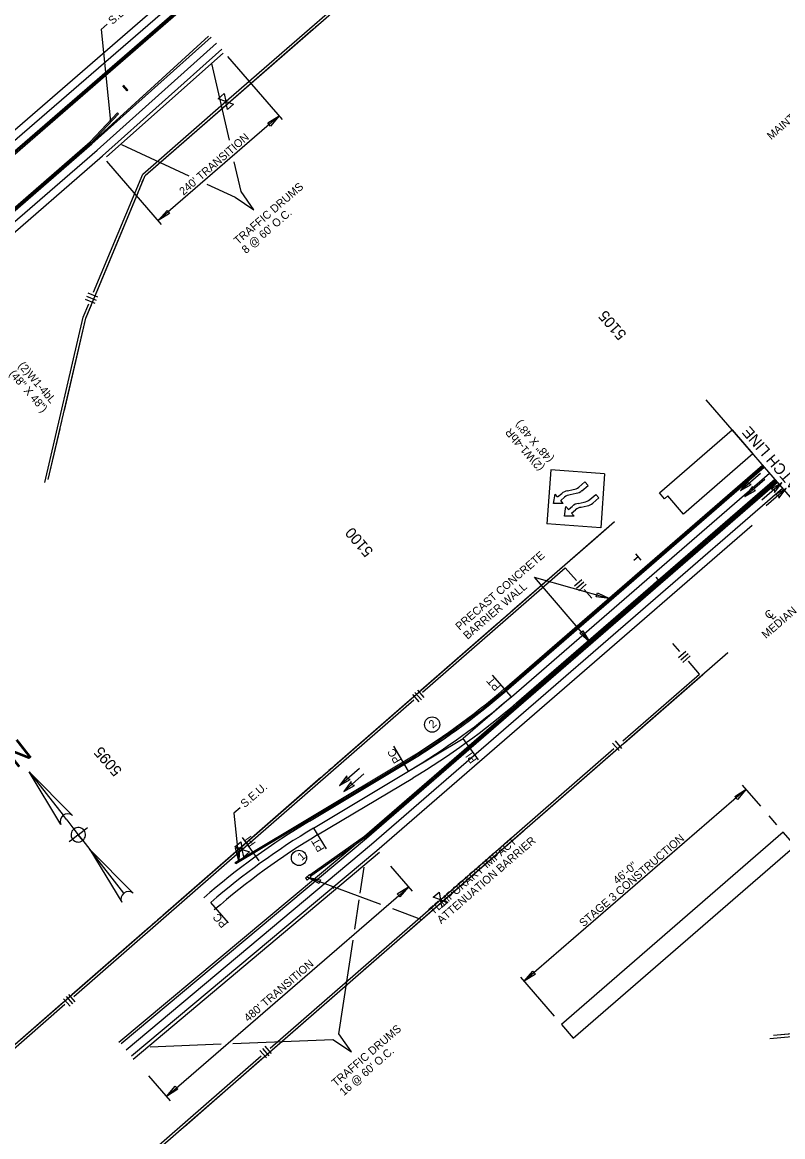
# Model space of a CAD drawing. Extents: x 259983 to 267998, y 211467 to 219827.
# Drawn here: x 263924 to 265064, y 214746 to 216417 of the extents above; entities that cross this region are included whole.
import ezdxf

# ---------------------------------------------------------------- set-up
doc = ezdxf.new("R2010")
doc.units = 0
for name, color, linetype in [('1', 7, 'Continuous'), ('DRAINAGE', 7, 'Continuous'), ('Level 1', 7, 'Continuous'), ('Level 43', 7, 'Continuous'), ('Level 58', 7, 'Continuous'), ('R-W - CofA', 7, 'Continuous'), ('R_MOT', 7, 'Continuous'), ('R_MOT STAGE 1', 7, 'Continuous'), ('R_MOT STAGE 2', 7, 'Continuous'), ('STATIONING1', 7, 'Continuous')]:
    doc.layers.add(name, color=color, linetype=linetype)

msp = doc.modelspace()

# ---------------------------------------------------------------- linework, layer by layer
at = {"layer": '1'}
for p, q in [((264051, 216413.6), (264042.1, 216405.9)), ((264042.1, 216405.9), (264056.1, 216267.8)), ((264691.6, 215585.1), (264804.6, 215552.9)), ((264691.6, 215585.1), (264775.2, 215487.6)), ((265031.6, 215241.6), (265004.3, 215273)), ((265009.6, 215267), (264676.8, 214979)), ((264250.5, 215239.1), (264241.2, 215231.1)), ((264241.2, 215231.1), (264248.6, 215159.4)), ((265055.7, 215213.6), (265044, 215227.2)), ((264461.7, 215094.3), (264351.4, 215135.2)), ((264523.3, 215071.4), (264479.6, 215087.6)), ((264532.1, 215079.1), (264523.3, 215071.4)), ((264722, 214926.8), (264671.4, 214985.4))]:
    msp.add_line(p, q, dxfattribs=at)
for points in [[(264234.5, 216240.1), (264208.1, 216354.8)], [(264072.9, 216233.3), (264173.6, 216186.5)], [(264200.6, 216174), (264243.1, 216154.3), (264271.2, 216135.7), (264252.2, 216162.9), (264241.9, 216207.6)], [(264430.6, 215111.2), (264436.5, 215149.9)], [(264422.5, 215057.3), (264429.2, 215101.4)], [(264239.5, 214885.8), (264389.8, 214891.9), (264417.9, 214873.4), (264398.9, 214900.5), (264420, 215040.7)], [(264115.9, 214880.8), (264222.2, 214885.1)]]:
    msp.add_lwpolyline(points, dxfattribs=at)
for points in [[(264292.4, 216265.7), (264309.4, 216276.4), (264296.4, 216261.1)], [(264144.9, 216129.9), (264127.9, 216119.3), (264141, 216134.5)], [(264786.4, 215561.2), (264804.6, 215552.9), (264784.8, 215555.4)], [(264764.6, 215504.6), (264775.2, 215487.6), (264760.1, 215500.7)], [(264992.6, 215256.3), (265009.6, 215267), (264996.6, 215251.7)], [(264249.6, 215179.4), (264248.6, 215159.4), (264243.6, 215178.8)], [(264369, 215125.5), (264351.4, 215135.2), (264371, 215131.1)], [(264486, 215110), (264502.9, 215120.7), (264489.9, 215105.5)], [(264693.8, 214989.7), (264676.8, 214979), (264689.8, 214994.3)], [(264157, 214817.2), (264140, 214806.5), (264153, 214821.7)]]:
    msp.add_lwpolyline(points, close=True, dxfattribs=at)
at = {"layer": 'DRAINAGE'}
for p, q in [((264081.2, 216313.8), (264074.7, 216321.3)), ((264082.4, 216314.8), (264075.8, 216322.3)), ((264081.2, 216313.8), (264082.4, 216314.8))]:
    msp.add_line(p, q, dxfattribs=at)
at = {"layer": 'Level 1'}
for p, q in [((263934.2, 215293.1), (263999, 215227.7)), ((263981.9, 215214.3), (263934.2, 215293.1)), ((263934.2, 215293.1), (263985.1, 215227.9)), ((263990.5, 215221), (263985.1, 215227.9)), ((263990.5, 215221), (264001.2, 215207.3)), ((264001.2, 215207.3), (264007.9, 215198.7)), ((264007.9, 215198.7), (264016.5, 215205.4)), ((264016.5, 215205.4), (264021.6, 215209.5)), ((264016.5, 215205.4), (264016.5, 215205.4)), ((263999, 215191.8), (263994.2, 215188)), ((264007.9, 215198.7), (263999.6, 215192.2)), ((264007.9, 215198.7), (264014.6, 215190.2)), ((264014.6, 215190.2), (264007.9, 215198.7)), ((264014.6, 215190.2), (264025.3, 215176.4)), ((264025.3, 215176.4), (264073, 215097.7)), ((264076.2, 215111.2), (264025.3, 215176.4)), ((264025.3, 215176.4), (264090.2, 215111.1))]:
    msp.add_line(p, q, dxfattribs=at)
for centre, radius, start, end in [((263992, 215219.1), 11.2, 128, 205.3196), ((263992, 215219.1), 11.2, 50.6804, 128), ((264007.9, 215198.7), 10.9, 128, 218), ((264007.9, 215198.7), 10.9, 38, 128), ((264007.9, 215198.7), 10.9, 308, 38), ((264007.9, 215198.7), 10.9, 218, 308), ((264083.1, 215102.4), 11.2, 128, 205.3196), ((264083.1, 215102.4), 11.2, 50.6804, 128)]:
    msp.add_arc(centre, radius, start, end, dxfattribs=at)
at = {"layer": 'Level 43'}
for points in [[(265001.2, 215714.8), (265031.3, 215740.7)], [(265007.8, 215706), (265037.8, 215732)], [(265063, 215726.4), (265033, 215700.4)], [(265069.6, 215717.7), (265039.6, 215691.7)], [(264399.6, 215272.5), (264429.7, 215298.5)], [(264406.2, 215263.8), (264436.2, 215289.8)]]:
    msp.add_lwpolyline(points, dxfattribs=at)
at = {"layer": 'Level 58'}
for points in [[(265012.4, 215729.4), (265001.2, 215714.8), (265017.3, 215723.7), (265012.6, 215724.6)], [(265051.9, 215711.8), (265063, 215726.4), (265047, 215717.5), (265051.7, 215716.6)], [(265018.9, 215720.7), (265007.8, 215706), (265023.8, 215715), (265019.1, 215715.9)], [(265058.4, 215703.1), (265069.6, 215717.7), (265053.5, 215708.7), (265058.2, 215707.9)], [(264410.8, 215287.2), (264399.6, 215272.5), (264415.7, 215281.5), (264411, 215282.4)], [(264417.4, 215278.4), (264406.2, 215263.8), (264422.2, 215272.8), (264417.5, 215273.6)]]:
    msp.add_lwpolyline(points, close=True, dxfattribs=at)
at = {"layer": 'R-W - CofA'}
for p, q in [((264217.7, 216301.9), (264226.9, 216309.9)), ((264226.9, 216309.9), (264229.3, 216297.9)), ((264229.3, 216297.9), (264217.7, 216301.9)), ((264231.6, 216285.9), (264229.3, 216297.9)), ((264229.3, 216297.9), (264240.8, 216294)), ((264240.8, 216294), (264231.6, 216285.9)), ((264020.2, 216006.3), (264034.5, 216000.3)), ((264022.2, 216011), (264036.5, 216005.1)), ((264018.2, 216001.5), (264032.6, 215995.5)), ((263962.8, 215731.4), (264019.3, 215973.1)), ((264738.3, 215599), (264755.1, 215579.7)), ((264752.1, 215572), (264763.1, 215581.6)), ((264755.3, 215568.3), (264766.3, 215578)), ((264758.5, 215564.6), (264769.5, 215574.3)), ((264766.6, 215566.5), (264778.1, 215553.3)), ((264910, 215473.4), (264899.7, 215485.3)), ((264908.2, 215464.4), (264919.2, 215474)), ((264911.4, 215460.7), (264922.4, 215470.3)), ((264914.6, 215457), (264925.6, 215466.7)), ((264939.4, 215439.7), (264922.9, 215458.7)), ((264509.2, 215409), (264518.8, 215398)), ((264512.8, 215412.2), (264522.5, 215401.2)), ((264516.5, 215415.4), (264526.1, 215404.4)), ((264812.9, 215339.4), (264822.7, 215328.2)), ((264809.2, 215336.1), (264818.9, 215324.9)), ((264242.9, 215180.5), (264251.6, 215188.1)), ((264251.6, 215188.1), (264253.8, 215176.8)), ((264253.8, 215176.8), (264242.9, 215180.5)), ((264256, 215165.5), (264253.8, 215176.8)), ((264253.8, 215176.8), (264264.7, 215173.1)), ((264264.7, 215173.1), (264256, 215165.5)), ((264540.1, 215105.2), (264548.9, 215112.8)), ((264551.1, 215101.4), (264540.1, 215105.2)), ((264548.9, 215112.8), (264551.1, 215101.4)), ((264553.4, 215090), (264551.1, 215101.4)), ((264551.1, 215101.4), (264562.1, 215097.7)), ((264562.1, 215097.7), (264553.4, 215090)), ((263989.5, 214956.2), (263999.2, 214945.2)), ((263993.2, 214959.4), (264002.8, 214948.4)), ((263985.8, 214953), (263995.5, 214942)), ((265050.7, 214898.1), (265362.9, 214926.4)), ((264280.3, 214875.2), (264290, 214864.1)), ((264284, 214878.5), (264293.7, 214867.3)), ((264287.7, 214881.7), (264297.4, 214870.6))]:
    msp.add_line(p, q, dxfattribs=at)
for points in [[(264019.3, 215973.1), (264108, 216186.8), (264635.8, 216646.6), (264947.8, 216943)], [(264233.9, 216301.9), (264501.9, 216535.5)], [(264363.9, 216409.7), (264368.6, 216413.8)], [(264236.6, 216298.8), (264359.9, 216406.2)], [(264030.9, 216011.9), (264104.5, 216189.2), (264233.9, 216301.9)], [(264108.7, 216187.3), (264236.6, 216298.8)], [(264103.9, 216176.9), (264106.3, 216182.7)], [(264034.8, 216010.3), (264097.5, 216161.4)], [(264099.5, 216166.2), (264101.9, 216172)], [(263957.5, 215726.7), (264015.4, 215974.4), (264023.8, 215994.7)], [(263987, 215834.9), (264019.3, 215973.1), (264027.6, 215993.1)], [(263984.4, 215823.6), (263985.8, 215829.8)], [(263962.8, 215731.4), (263980.5, 215807.3)], [(263981.7, 215812.4), (263983.2, 215818.5)], [(263865, 214843.2), (264812.1, 215668.4)], [(264778.9, 215639.5), (264812.1, 215668.4)], [(264658.2, 215534.4), (264778.9, 215639.5)], [(264524.3, 215412.5), (264738.3, 215599)], [(264641.8, 215520), (264646.3, 215523.9)], [(264650, 215527.2), (264654.5, 215531.1)], [(264521.7, 215415.4), (264638, 215516.8)], [(264029.2, 214641.4), (264982.3, 215471.9)], [(264965.1, 215456.9), (264982.3, 215471.9)], [(264824.5, 215339.6), (264939.4, 215439.7)], [(264827.1, 215336.6), (264944.7, 215439.1)], [(264948.4, 215442.4), (264953, 215446.3)], [(264956.8, 215449.6), (264961.3, 215453.6)], [(264258.2, 215180.6), (264511, 215400.9)], [(264392.1, 215302.5), (264508.5, 215403.9)], [(264555.5, 215105.2), (264811.1, 215327.9)], [(264696.1, 215222.5), (264813.7, 215325)], [(264375.7, 215288.2), (264380.2, 215292.1)], [(264383.9, 215295.3), (264388.4, 215299.2)], [(264255.6, 215183.5), (264371.9, 215284.9)], [(264558.1, 215102.3), (264675.7, 215204.7)], [(264679.5, 215208), (264684, 215212)], [(264687.8, 215215.3), (264692.3, 215219.2)], [(264001, 214956.5), (264258.2, 215180.6)], [(264134.9, 215078.4), (264255.6, 215183.5)], [(264295.5, 214878.7), (264555.5, 215105.2)], [(264436.1, 214996), (264558.1, 215102.3)], [(264126.7, 215071.2), (264131.2, 215075.1)], [(263998.4, 214959.4), (264114.7, 215060.8)], [(264118.5, 215064.1), (264123, 215068)], [(264427.8, 214988.7), (264432.4, 214992.7)], [(264298.1, 214875.8), (264415.7, 214978.2)], [(264419.5, 214981.5), (264424, 214985.5)], [(263865, 214838), (263987.7, 214944.9)], [(263868.8, 214846.5), (263985.1, 214947.9)], [(265045.3, 214893.4), (265351, 214921.1)], [(265050.7, 214898.1), (265155.8, 214907.6)], [(264026.6, 214644.4), (264282.1, 214867.1)], [(264167.2, 214761.6), (264284.7, 214864.1)], [(264158.8, 214754.4), (264163.4, 214758.3)], [(264150.5, 214747.1), (264155.1, 214751.1)]]:
    msp.add_lwpolyline(points, dxfattribs=at)
at = {"layer": 'R_MOT'}
for p, q in [((264716.5, 215745.6), (264710.7, 215664.8)), ((264797.3, 215739.8), (264716.5, 215745.6)), ((264797.3, 215739.8), (264791.5, 215659)), ((264758.7, 215719.9), (264767.8, 215727.8)), ((264763.3, 215714.5), (264772.4, 215722.4)), ((264772.4, 215722.4), (264767.8, 215727.8)), ((264720.7, 215695.1), (264722.9, 215709.5)), ((264726.8, 215705.1), (264722.9, 215709.5)), ((264726.8, 215705.1), (264732.9, 215710.4)), ((264741.5, 215714.1), (264750, 215716.2)), ((264745.7, 215708.6), (264754.7, 215710.8)), ((264775, 215701.1), (264784.1, 215708.9)), ((264788.8, 215703.6), (264784.1, 215708.9)), ((264735.3, 215695.2), (264720.7, 215695.1)), ((264731.4, 215699.7), (264737.2, 215704.6)), ((264735.3, 215695.2), (264731.4, 215699.7)), ((264737, 215676.3), (264739.2, 215690.7)), ((264743.1, 215686.2), (264739.2, 215690.7)), ((264743.1, 215686.2), (264749.3, 215691.5)), ((264757.8, 215695.3), (264766.4, 215697.3)), ((264762, 215689.8), (264771, 215692)), ((264779.6, 215695.7), (264788.8, 215703.6)), ((264751.6, 215676.3), (264737, 215676.3)), ((264747.8, 215680.8), (264753.5, 215685.8)), ((264751.6, 215676.3), (264747.8, 215680.8)), ((264791.5, 215659), (264710.7, 215664.8)), ((264847.4, 215615.2), (264840.9, 215609.6)), ((264843.4, 215619.8), (264851.4, 215610.5)), ((264878, 215580.3), (264871.5, 215574.7)), ((264874, 215584.9), (264882, 215575.6))]:
    msp.add_line(p, q, dxfattribs=at)
for centre, major_axis in [((264744.8, 215697.2), (-11.6, 13.4)), ((264749.1, 215691.5), (-11.6, 13.4)), ((264746.7, 215733.1), (11.6, -13.4)), ((264751.4, 215727.7), (11.6, -13.4)), ((264761.1, 215678.4), (-11.6, 13.4)), ((264765.4, 215672.6), (-11.6, 13.4)), ((264763, 215714.3), (11.6, -13.4)), ((264767.8, 215708.8), (11.6, -13.4))]:
    msp.add_ellipse(centre, major_axis=major_axis, ratio=0.9, start_param=5.717125, end_param=6.306311, dxfattribs=at)
at = {"layer": 'R_MOT STAGE 1'}
for p, q in [((263578.6, 215966.6), (264310.4, 216600.1)), ((264298.4, 216555.3), (263057.4, 215481)), ((264299.6, 216553.8), (263058.7, 215479.5)), ((263048.2, 215491.5), (264237, 216520.7)), ((263056, 215482.5), (264244.9, 216511.7)), ((264028.2, 216234.2), (264207, 216394.3)), ((264029.5, 216237.2), (264203.1, 216395.9)), ((264036.2, 216225.2), (264215, 216385.3)), ((264044.2, 216216.3), (264223, 216376.4)), ((264050.1, 216215.1), (264225, 216370.4)), ((264066.8, 216280.8), (264025.6, 216237.2)), ((264068.3, 216279.4), (264027, 216235.8)), ((264068.3, 216279.4), (264027, 216235.8)), ((264066.8, 216280.8), (264068.3, 216279.4)), ((264066.8, 216280.8), (264068.3, 216279.4)), ((263286.2, 215594.4), (264026.9, 216235.7)), ((263287.5, 215592.9), (264028.2, 216234.2)), ((263452.2, 215740.7), (264025.6, 216237.2)), ((263819.5, 216037.6), (264036.2, 216225.2)), ((264025.6, 216237.2), (264027, 216235.8)), ((264026.9, 216235.7), (264025.6, 216237.2)), ((264025.6, 216237.2), (264027, 216235.8)), ((264026.9, 216235.7), (264025.6, 216237.2)), ((263471.1, 215720.1), (264044.2, 216216.3)), ((265116.5, 215657.7), (264949.5, 215850.6)), ((264646.9, 215417.7), (265034.1, 215752.8)), ((264648.3, 215416.2), (265035.4, 215751.3)), ((264649.6, 215414.7), (265036.7, 215749.8)), ((264657.4, 215405.6), (265044.6, 215740.7)), ((264437.1, 215196.4), (265053.7, 215730.2)), ((264438.5, 215194.9), (265055, 215728.6)), ((264440.1, 215193.6), (265056.4, 215727.1)), ((264665.3, 215396.5), (265052.4, 215731.7)), ((264447.8, 215184.5), (265064.2, 215718.1)), ((264455.6, 215175.3), (265018.8, 215662.9)), ((264657.4, 215405.6), (264629.2, 215438.2)), ((264657.4, 215405.6), (264585.2, 215343.1)), ((264503.3, 215294.1), (264585.2, 215343.1)), ((264608.3, 215311.2), (264585.2, 215343.1)), ((264503.3, 215294.1), (264480.9, 215331.4)), ((264243.2, 215157.2), (264495.1, 215307.8)), ((264244.3, 215155.5), (264496.1, 215306.1)), ((264354.6, 215219.1), (264497.1, 215304.4)), ((264360.8, 215208.8), (264503.3, 215294.1)), ((264366.9, 215198.5), (264509.5, 215283.8)), ((264360.8, 215208.8), (264379.5, 215177.5)), ((264068.7, 214887.6), (264439.9, 215197.6)), ((264072.1, 214885.6), (264440.2, 215193.7)), ((264253.6, 215194.7), (264278.8, 215159.8)), ((264355.4, 215138.8), (264437.1, 215196.4)), ((264356.6, 215137.1), (264438.3, 215194.7)), ((264437.1, 215196.4), (264438.3, 215194.7)), ((264437.1, 215196.4), (264438.5, 215194.9)), ((264079.8, 214876.4), (264447.9, 215184.5)), ((264087.5, 214867.2), (264455.6, 215175.3)), ((264090.4, 214862.3), (264459.7, 215172.4)), ((264244.3, 215155.5), (264243.2, 215157.2)), ((264356.6, 215137.1), (264355.4, 215138.8)), ((264390.4, 215119.4), (264391.4, 215118.3)), ((264233.3, 215066.5), (264206.6, 215097.3))]:
    msp.add_line(p, q, dxfattribs=at)
msp.add_lwpolyline([(264354.8, 215139.1), (264348.5, 215133.7), (264351, 215130.8), (264357.3, 215136.3)], close=True, dxfattribs=at)
for centre in [(264538.6, 215363.9), (264338.9, 215164)]:
    msp.add_circle(centre, 11.4, dxfattribs=at)
for centre, radius, start, end in [((263943.1, 216230.7), 1075.3, 300.8833, 310.8833), ((263943.1, 216230.7), 1077.3, 300.8833, 310.8833), ((263943.1, 216230.7), 1079.3, 300.8833, 310.8833), ((263943.1, 216230.7), 1091.3, 300.8833, 310.8833), ((263943.1, 216230.7), 1103.3, 300.8833, 310.8833), ((264920.9, 214272.2), 1103.3, 120.8833, 131.0667), ((264920.9, 214272.2), 1091.3, 120.8833, 130.8833), ((264920.9, 214272.2), 1079.3, 120.8833, 131.0667)]:
    msp.add_arc(centre, radius, start, end, dxfattribs=at)
at = {"layer": 'R_MOT STAGE 2'}
for p, q in [((264314.2, 216270.8), (264232.2, 216365.5)), ((264309.4, 216276.4), (264127.9, 216119.3)), ((264132.8, 216113.7), (264050.7, 216208.5)), ((264476.1, 215151.6), (264508.7, 215114)), ((264140.3, 214806.2), (264503.2, 215120.4)), ((264113.2, 214837.5), (264145.8, 214799.8))]:
    msp.add_line(p, q, dxfattribs=at)
for points in [[(264931.7, 215693.3), (264915.8, 215679.5), (264892.2, 215706.7), (264887.2, 215702.4), (264879.6, 215711.1), (264988.6, 215805.5), (265019.5, 215769.8)], [(264732.4, 214914.4), (264750.2, 214893.8), (265083.1, 215182), (265065.3, 215202.6)]]:
    msp.add_lwpolyline(points, close=True, dxfattribs=at)

# ---------------------------------------------------------------- texts
at = {"layer": '1'}
for s, rotation, p in [('S.E.U.', 40.8733, (264059.2, 216412.6)), ("240' TRANSITION", 40.8733, (264165.7, 216156.6)), ('TRAFFIC DRUMS', 40.8921, (264247.6, 216082.7)), ("8 @ 60' O.C.", 40.8921, (264259.4, 216069.1)), ('PRECAST CONCRETE', 40.8833, (264579.9, 215504.4)), ('BARRIER WALL', 40.8833, (264591.7, 215490.8)), ('MEDIAN', 40.8933, (265039.3, 215492)), ('C', 40.8933, (265043.6, 215521)), ('L', 40.8933, (265048.8, 215520.2)), ('2', 40.8733, (264539.7, 215357.6)), ('S.E.U.', 40.8733, (264257.5, 215238.6)), ('TEMPORARY IMPACT', 40.8733, (264540.4, 215078.1)), ('ATTENUATION BARRIER', 40.8733, (264552.2, 215064.5)), ('1', 40.8733, (264343.1, 215159.1)), ("480' TRANSITION", 40.8733, (264262.7, 214917.5)), ('TRAFFIC DRUMS', 40.8921, (264394.3, 214820.3)), ("16 @ 60' O.C.", 40.8921, (264406.1, 214806.7))]:
    msp.add_text(s, height=12, rotation=rotation, dxfattribs=at).set_placement(p)
at = {"layer": 'Level 1'}
for s, height, rotation, p in [('MAINTENANCE OF TRAFFIC', 11.7, 40.8733, (265047.1, 216239.9)), ('N', 34.2, 38, (263914.9, 215297.2))]:
    msp.add_text(s, height=height, rotation=rotation, dxfattribs=at).set_placement(p)
at = {"layer": 'R_MOT'}
for s, rotation, p in [('(2)W1-4bL', 310.8833, (263917, 215901.6)), ('(48" X 48")', 310.8833, (263903.4, 215889.2)), ('(2)W1-4bR', 130.8833, (264707.4, 215750)), ('(48" X 48")', 130.8833, (264721.4, 215762.8))]:
    msp.add_text(s, height=12, rotation=rotation, dxfattribs=at).set_placement(p)
at = {"layer": 'R_MOT STAGE 1'}
for s, rotation, p in [('PT', 130.8833, (264642, 215420.9)), ('PC', 120.8833, (264492.5, 215310.2)), ('PI', 125.8833, (264606.3, 215311.2)), ('PI', 125.8833, (264274.8, 215186.3)), ('PT', 120.8833, (264377.7, 215177.6)), ('PC', 130.8833, (264232.3, 215065.5))]:
    msp.add_text(s, height=12, rotation=rotation, dxfattribs=at).set_placement(p)
at = {"layer": 'R_MOT STAGE 2'}
for s, p in [('STAGE 3 CONSTRUCTION', (264765.5, 215059.8)), ('46\'-0"', (264816.3, 215123.7))]:
    msp.add_text(s, height=12, rotation=40.8833, dxfattribs=at).set_placement(p)
at = {"layer": 'STATIONING1'}
for s, p in [('5105', (264831.1, 215949.2)), ('MATCH LINE', (265102.1, 215711.3)), ('5100', (264451.3, 215624)), ('5095', (264074.5, 215295.3))]:
    msp.add_text(s, height=16.5, rotation=130.8833, dxfattribs=at).set_placement(p)

doc.saveas('drawing.dxf')
